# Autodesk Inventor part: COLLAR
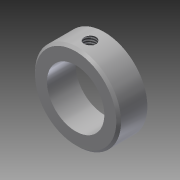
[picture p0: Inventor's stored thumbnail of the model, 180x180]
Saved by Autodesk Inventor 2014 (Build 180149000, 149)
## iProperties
Shininess: 64.0
Length Units: 11272
Angle Units: 11279
Time Units: 11290
Mass Units: 11286
Length Display Precision: 3
Angle Display Precision: 2
Compacted: True
Part Number: COLLAR
Document SubType Name: Modeling
Created: 2003-11
Designer: Autodesk, Inc.
Manufacturer: Standard
Standards Organization: Custom
Mass: 25.9974 g
Surface Area: 21.2895 cm^2
Volume: 3.30755 cm^3
Density: 7.86 g/cm^3
Material: Steel, Mild
Appearance: Steel
Density: 0.0
Volumn: 0.0
Area: 0.0
PropertySet Name: Model Information
Control State: 0
Master: False
Checked Out: False
Author: Autodesk, Inc.
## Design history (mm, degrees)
sketch "Sketch1"
  geometry: C1 r 14.287 at (0, 0); C2 r 9.525 at (0, 0); 1 further point
  constraints: 2 centre point, 2 coincident
  dimensions: "d0" = 28.575 diameter of C1; "d1" = 19.05 diameter of C2
extrude "Extrusion1" new body sketch "Sketch1" distance "d2" = 9.525; taper "d3" = 0 deg
chamfer "Chamfer1" distance "d4" = 0.7874; stored, may be unused: second distance "d5" = 3.175, angle "d16" = 45 deg
sketch "Sketch3"
  geometry: L1 (-14.287, 0)-(14.287, 0) reference; L2 (14.287, 8.738)-(-14.287, 8.738) reference; L3 (14.287, 0)-(14.287, 8.738) reference; L4 (-14.287, 0)-(-14.287, 8.738) reference; L5 (0, 0)-(0, 8.738); 1 further point
  constraints: 2 end point, 2 midpoint, 1 point on line
  dimensions: "d8" = 4.7625 distance from line of L1 point (0, 4.763)
hole "Hole1" sketch "Sketch3" at (0, 4.763) diameter "d9" = 3.9624; stored, may be unused: countersink angle "d13" = 82 deg, drill point angle "d15" = 118 deg; dims "d10" = 12.7, "d11" = 9.525, "d12" = 6.35, "d14" = 19.05
body "Solid1"
